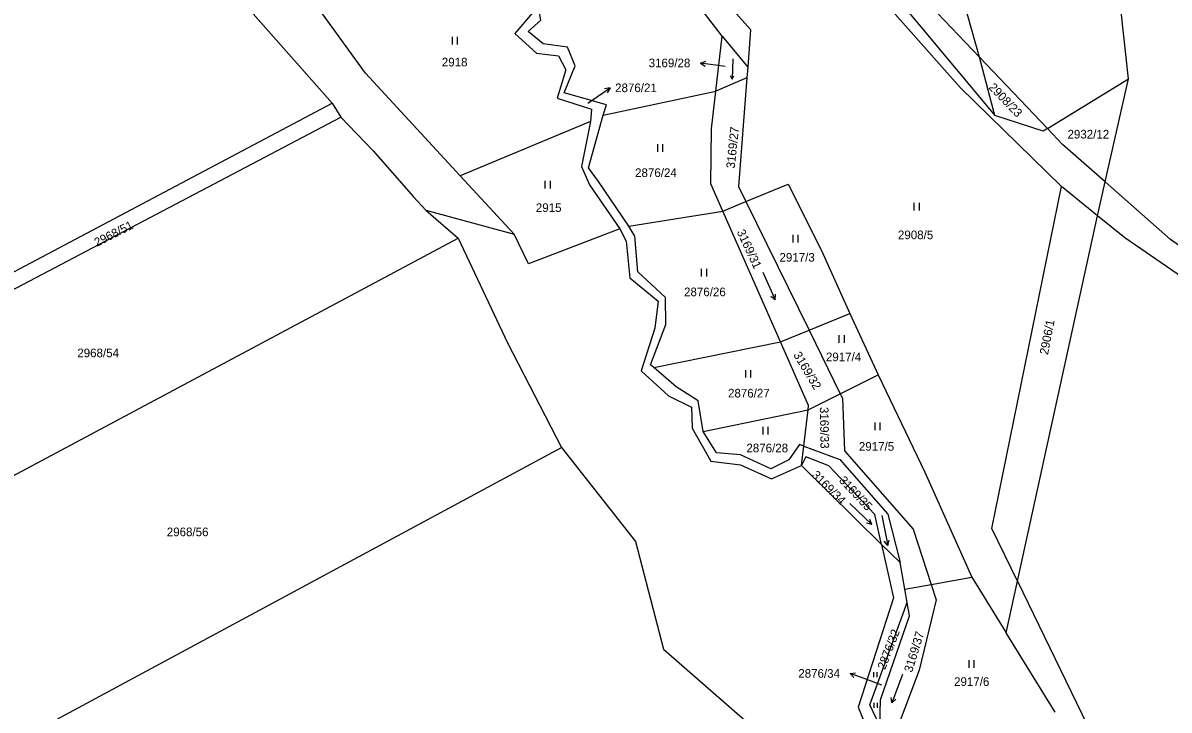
# Model space of a CAD drawing. Extents: x -776734 to -748832, y -1118122 to -976986.
# Drawn here: x -754304.9 to -754079.1, y -1114231.2 to -1114095.9 of the extents above; entities that cross this region are included whole.
import ezdxf

# ---------------------------------------------------------------- set-up
doc = ezdxf.new("R2010")
doc.units = 0
for name, color, linetype in [('KM_Hranice parcel', 7, 'Continuous'), ('KM_Parcelní čísla', 7, 'Continuous'), ('KM_Pop  PČ popisy', 7, 'Continuous'), ('KM_Značky kultur', 7, 'Continuous')]:
    doc.layers.add(name, color=color, linetype=linetype)

msp = doc.modelspace()

# ---------------------------------------------------------------- linework, layer by layer
at = {"layer": 'KM_Hranice parcel'}
for p, q in [((-754087.11, -1114106.92), (-754088.55, -1114093.73)), ((-754168.44, -1114109.35), (-754167.2, -1114098.53)), ((-754167.2, -1114098.53), (-754162.14, -1114104.59)), ((-754103.08, -1114116.7), (-754116.48, -1114102.61)), ((-754113.46, -1114114.09), (-754116.48, -1114102.61)), ((-754162.14, -1114104.59), (-754162.3, -1114106.68)), ((-754162.3, -1114106.68), (-754168.44, -1114109.35)), ((-754103.08, -1114116.7), (-754087.11, -1114106.92)), ((-754091.71, -1114127.19), (-754087.11, -1114106.92)), ((-754190.62, -1114114.05), (-754168.44, -1114109.35)), ((-754369.27, -1114177.97), (-754244.03, -1114111.7)), ((-754244.03, -1114111.7), (-754242.27, -1114114.46)), ((-754367.97, -1114180.55), (-754242.27, -1114114.46)), ((-754193.1, -1114115.27), (-754218.77, -1114126.01)), ((-754208.18, -1114137.47), (-754218.77, -1114126.01)), ((-754093.22, -1114133.86), (-754100.3, -1114128.12)), ((-754093.22, -1114133.86), (-754091.71, -1114127.19)), ((-754225.54, -1114132.73), (-754208.18, -1114137.47)), ((-754225.54, -1114132.73), (-754219.21, -1114138.3)), ((-754185.59, -1114135.89), (-754167.01, -1114132.95)), ((-754167.01, -1114132.95), (-754162.48, -1114131.08)), ((-754155.67, -1114158.7), (-754167.01, -1114132.95)), ((-754162.48, -1114131.08), (-754150.05, -1114156.4)), ((-754108.98, -1114205.82), (-754093.22, -1114133.86)), ((-754205.3, -1114143.34), (-754208.18, -1114137.47)), ((-754187.36, -1114136.45), (-754205.3, -1114143.34)), ((-754352.59, -1114209.41), (-754219.21, -1114138.3)), ((-754150.05, -1114156.4), (-754141.99, -1114153.11)), ((-754141.99, -1114153.11), (-754136.43, -1114165.22)), ((-754155.67, -1114158.7), (-754150.05, -1114156.4)), ((-754150.05, -1114156.4), (-754143.89, -1114168.94)), ((-754180.63, -1114163.75), (-754155.67, -1114158.7)), ((-754143.89, -1114168.94), (-754136.43, -1114165.22)), ((-754150.25, -1114172.1), (-754143.89, -1114168.94)), ((-754170.9, -1114176.36), (-754150.25, -1114172.1)), ((-754151.11, -1114179.23), (-754150.25, -1114172.1)), ((-754330.63, -1114250.42), (-754198.85, -1114179.51)), ((-754151.57, -1114183.02), (-754151.11, -1114179.23)), ((-754135.75, -1114198.57), (-754151.57, -1114183.02)), ((-754132.12, -1114202.14), (-754135.75, -1114198.57)), ((-754131.18, -1114207.42), (-754132.12, -1114202.14)), ((-754126, -1114206.49), (-754118, -1114205.06)), ((-754118, -1114205.06), (-754111.21, -1114215.97)), ((-754131.18, -1114207.42), (-754126, -1114206.49)), ((-754130.72, -1114210.04), (-754131.18, -1114207.42)), ((-754111.21, -1114215.97), (-754108.98, -1114205.82)), ((-754101.58, -1114231.65), (-754111.21, -1114215.97))]:
    msp.add_line(p, q, dxfattribs=at)
for points in [[(-754116.48, -1114102.61), (-754123.48, -1114077.66), (-754132.04, -1114047.82)], [(-754116.48, -1114102.61), (-754131.66, -1114086.65), (-754163.43, -1114050.7)], [(-754265.87, -1114060.4), (-754264.1, -1114088.9), (-754244.03, -1114111.7)], [(-754166.63, -1114060.81), (-754158.51, -1114060.11), (-754113.46, -1114114.09)], [(-754100.3, -1114128.12), (-754120.26, -1114108.63), (-754140.25, -1114086.01), (-754165.09, -1114061.97), (-754166.63, -1114060.81)], [(-754187.12, -1114062.98), (-754179.33, -1114077.31), (-754161.57, -1114097.18), (-754162.14, -1114104.59)], [(-754167.2, -1114098.53), (-754182.93, -1114077.93), (-754186.05, -1114073.02)], [(-754190.62, -1114114.05), (-754189.96, -1114112.02), (-754198.28, -1114109.63), (-754196.12, -1114104.32), (-754197.62, -1114100.64), (-754202.44, -1114099.98), (-754205.36, -1114097.55), (-754202.87, -1114095.32), (-754203.76, -1114090.47), (-754204.36, -1114088.35), (-754210.92, -1114090.38), (-754212.95, -1114086.67), (-754213.4, -1114082.24), (-754210.14, -1114080.45), (-754210.68, -1114078.71)], [(-754215.05, -1114080.73), (-754214.85, -1114087.87), (-754212.07, -1114092.28), (-754205.62, -1114090.24), (-754205.26, -1114091.17), (-754204.54, -1114093.92), (-754208, -1114097.94), (-754203.75, -1114101.83), (-754199.39, -1114102.37), (-754197.98, -1114105.1), (-754199.67, -1114110.73), (-754192.92, -1114112.88), (-754193.1, -1114115.27)], [(-754218.77, -1114126.01), (-754237.42, -1114105.81), (-754245.9, -1114094.07), (-754246.56, -1114092.91)], [(-754162.3, -1114106.68), (-754163.95, -1114128.1), (-754162.48, -1114131.08)], [(-754167.01, -1114132.95), (-754169.37, -1114127.59), (-754169.29, -1114116.77), (-754168.44, -1114109.35)], [(-754242.27, -1114114.46), (-754235.96, -1114121.09), (-754227.97, -1114130.14), (-754225.54, -1114132.73)], [(-754185.59, -1114135.89), (-754191.51, -1114127.15), (-754193.49, -1114124.4), (-754190.62, -1114114.05)], [(-754103.08, -1114116.7), (-754103.9, -1114117.22), (-754113.46, -1114114.09)], [(-754193.1, -1114115.27), (-754194.89, -1114124.19), (-754193.28, -1114127.78), (-754187.36, -1114136.45)], [(-754091.71, -1114127.19), (-754100.11, -1114119.82), (-754103.08, -1114116.7)], [(-754162.48, -1114131.08), (-754154.17, -1114127.65), (-754147.62, -1114140.7), (-754141.99, -1114153.11)], [(-754108.98, -1114205.82), (-754114.02, -1114195.42), (-754100.3, -1114128.12)], [(-754035.66, -1114168.37), (-754051.47, -1114157.88), (-754078.81, -1114138.51), (-754091.71, -1114127.19)], [(-754036.72, -1114172.95), (-754053.98, -1114161.51), (-754087.81, -1114138.24), (-754093.22, -1114133.86)], [(-754187.36, -1114136.45), (-754186.1, -1114138.84), (-754185.35, -1114146.09), (-754179.8, -1114150.68), (-754180.45, -1114156), (-754183.1, -1114164.4), (-754177.76, -1114169.33), (-754173.24, -1114171.54), (-754173.09, -1114175.71), (-754169.4, -1114182.18), (-754163.56, -1114182.94), (-754157.42, -1114185.64), (-754151.57, -1114183.02)], [(-754180.63, -1114163.75), (-754181.31, -1114163.21), (-754178.28, -1114155.29), (-754178.35, -1114149.94), (-754183.76, -1114144.93), (-754184.36, -1114137.91), (-754185.59, -1114135.89)], [(-754219.21, -1114138.3), (-754209.46, -1114158.87), (-754198.85, -1114179.51)], [(-754150.25, -1114172.1), (-754150.15, -1114171.23), (-754155.67, -1114158.7)], [(-754170.9, -1114176.36), (-754171.93, -1114170.29), (-754176.21, -1114167.53), (-754180.63, -1114163.75)], [(-754136.43, -1114165.22), (-754127.25, -1114184.33), (-754118, -1114205.06)], [(-754143.89, -1114168.94), (-754143.47, -1114169.8), (-754143.05, -1114180.16), (-754129.57, -1114195.6), (-754126, -1114206.49)], [(-754151.11, -1114179.23), (-754151.96, -1114178.92), (-754154.03, -1114181.96), (-754157.55, -1114183.73), (-754163.59, -1114180.95), (-754168.28, -1114180.53), (-754170.9, -1114176.36)], [(-754198.85, -1114179.51), (-754184.23, -1114198.03), (-754178.73, -1114219.2), (-754161.66, -1114234.11)], [(-754151.11, -1114179.23), (-754143.98, -1114181.84), (-754134.51, -1114192.65), (-754132.12, -1114202.14)], [(-754135.75, -1114198.57), (-754137.07, -1114192.7), (-754146.18, -1114183.1), (-754150.66, -1114181.35), (-754151.57, -1114183.02)], [(-754135.75, -1114198.57), (-754133.39, -1114209.08), (-754140.38, -1114230.64), (-754136.28, -1114240.53)], [(-754126, -1114206.49), (-754125.03, -1114209.47), (-754128.37, -1114223.34), (-754132.71, -1114234.86), (-754122.1, -1114241.5)], [(-754108.98, -1114205.82), (-754073.07, -1114279.85), (-754068.29, -1114298.13)], [(-754136.12, -1114234.32), (-754138.05, -1114230.19), (-754130.72, -1114210.04)], [(-754136.12, -1114234.32), (-754135.99, -1114229.21), (-754130.26, -1114212.66), (-754130.72, -1114210.04)]]:
    msp.add_lwpolyline(points, dxfattribs=at)
at = {"layer": 'KM_Pop  PČ popisy'}
for p, q in [((-754171.462, -1114103.782), (-754170.4, -1114103.426)), ((-754168.49, -1114104.2), (-754171.462, -1114103.782)), ((-754171.462, -1114103.782), (-754170.54, -1114104.418)), ((-754166.59, -1114104.47), (-754168.49, -1114104.2)), ((-754193.64, -1114111.67), (-754191.74, -1114110.37)), ((-754191.74, -1114110.37), (-754189.252, -1114108.692)), ((-754189.252, -1114108.692), (-754190.362, -1114108.837)), ((-754189.252, -1114108.692), (-754189.802, -1114109.667)), ((-754141.98, -1114223.994), (-754140.868, -1114223.866)), ((-754139.16, -1114225.02), (-754141.98, -1114223.994)), ((-754141.98, -1114223.994), (-754141.21, -1114224.807)), ((-754135.71, -1114226.29), (-754139.16, -1114225.02))]:
    msp.add_line(p, q, dxfattribs=at)
at = {"layer": 'KM_Značky kultur'}
for p, q in [((-754220.301, -1114100.15), (-754220.301, -1114098.65)), ((-754219.3, -1114100.15), (-754219.3, -1114098.65)), ((-754165.056, -1114102.933), (-754165.196, -1114106.95)), ((-754165.196, -1114106.95), (-754165.509, -1114106.284)), ((-754165.196, -1114106.95), (-754164.838, -1114106.307)), ((-754179.851, -1114121.28), (-754179.851, -1114119.78)), ((-754178.85, -1114121.28), (-754178.85, -1114119.78)), ((-754202.011, -1114128.47), (-754202.011, -1114126.97)), ((-754201.01, -1114128.47), (-754201.01, -1114126.97)), ((-754129.311, -1114132.85), (-754129.311, -1114131.35)), ((-754128.31, -1114132.85), (-754128.31, -1114131.35)), ((-754153.191, -1114139.13), (-754153.191, -1114137.63)), ((-754152.19, -1114139.13), (-754152.19, -1114137.63)), ((-754171.221, -1114145.8), (-754171.221, -1114144.3)), ((-754170.22, -1114145.8), (-754170.22, -1114144.3)), ((-754159.141, -1114144.949), (-754156.701, -1114150.43)), ((-754156.701, -1114150.43), (-754157.556, -1114149.741)), ((-754156.701, -1114150.43), (-754156.64, -1114149.333)), ((-754144.091, -1114158.91), (-754144.091, -1114157.41)), ((-754143.09, -1114158.91), (-754143.09, -1114157.41)), ((-754162.531, -1114165.74), (-754162.531, -1114164.24)), ((-754161.53, -1114165.74), (-754161.53, -1114164.24)), ((-754159.111, -1114176.92), (-754159.111, -1114175.42)), ((-754158.11, -1114176.92), (-754158.11, -1114175.42)), ((-754137.041, -1114176.1), (-754137.041, -1114174.6)), ((-754136.04, -1114176.1), (-754136.04, -1114174.6)), ((-754142.012, -1114190.524), (-754137.696, -1114194.692)), ((-754137.696, -1114194.692), (-754138.05, -1114193.653)), ((-754135.688, -1114192.904), (-754134.543, -1114198.793)), ((-754137.696, -1114194.692), (-754138.747, -1114194.374)), ((-754134.543, -1114198.793), (-754135.221, -1114197.93)), ((-754134.543, -1114198.793), (-754134.237, -1114197.738)), ((-754118.531, -1114222.9), (-754118.531, -1114221.4)), ((-754117.53, -1114222.9), (-754117.53, -1114221.4)), ((-754137.292, -1114224.74), (-754137.292, -1114223.735)), ((-754136.622, -1114224.74), (-754136.622, -1114223.735)), ((-754131.619, -1114224.192), (-754133.769, -1114229.794)), ((-754137.252, -1114230.76), (-754137.252, -1114229.755)), ((-754136.582, -1114230.76), (-754136.582, -1114229.755)), ((-754133.769, -1114229.794), (-754133.887, -1114228.702)), ((-754133.769, -1114229.794), (-754132.951, -1114229.061))]:
    msp.add_line(p, q, dxfattribs=at)

# ---------------------------------------------------------------- texts
at = {"layer": 'KM_Parcelní čísla'}
for s, p in [('2918', (-754222.4, -1114104.45)), ('3169/28', (-754181.653, -1114104.62)), ('2876/21', (-754188.26, -1114109.52)), ('2932/12', (-754099.13, -1114118.65)), ('2876/24', (-754184.32, -1114126.23)), ('2915', (-754203.88, -1114133.12)), ('2908/5', (-754132.54, -1114138.48)), ('2917/3', (-754155.88, -1114142.9)), ('2876/26', (-754174.68, -1114149.71)), ('2968/54', (-754294.22, -1114161.73)), ('2917/4', (-754146.73, -1114162.51)), ('2876/27', (-754166.02, -1114169.65)), ('2876/28', (-754162.39, -1114180.45)), ('2917/5', (-754140.24, -1114180.14)), ('2968/56', (-754276.59, -1114196.97)), ('2876/34', (-754152.173, -1114224.84)), ('2917/6', (-754121.48, -1114226.45))]:
    msp.add_text(s, height=1.7, dxfattribs=at).set_placement(p)
for s, rotation, p in [('2908/23', 313.999997, (-754114.791, -1114108.7)), ('3169/27', 84, (-754164.694, -1114124.608)), ('2968/51', 27, (-754290.354, -1114140.007)), ('3169/31', 295, (-754164.33, -1114137.029)), ('2906/1', 79, (-754102.985, -1114161.332)), ('3169/32', 301, (-754153.218, -1114161.247)), ('3169/33', 271, (-754147.929, -1114171.524)), ('3169/34', 315, (-754149.651, -1114185.071)), ('3169/35', 313, (-754144.261, -1114186.079)), ('2876/32', 68.999997, (-754135.076, -1114223.364)), ('3169/37', 73, (-754129.757, -1114223.898))]:
    msp.add_text(s, height=1.7, rotation=rotation, dxfattribs=at).set_placement(p)

doc.saveas('drawing.dxf')
